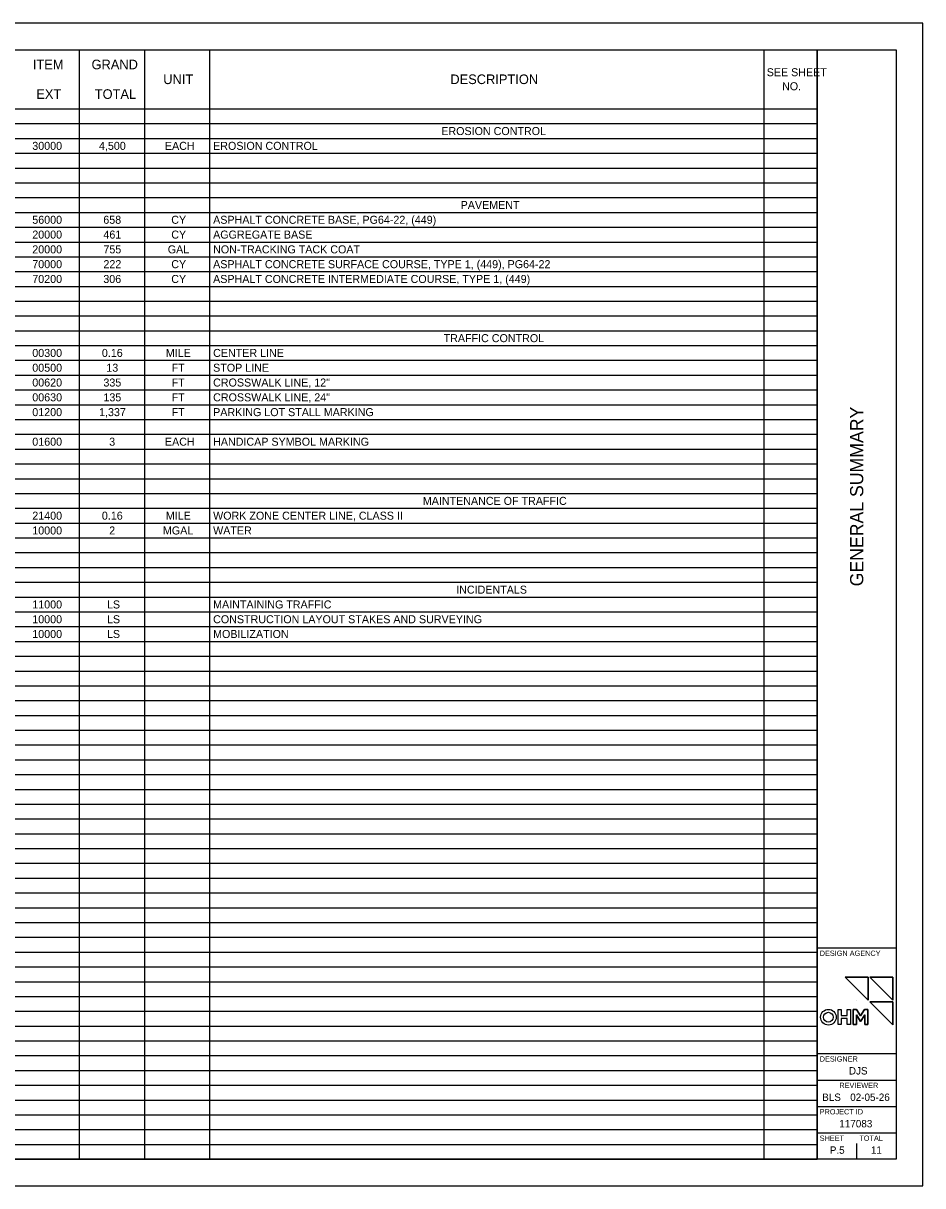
# Model space of a CAD drawing. Extents: x 0 to 34, y 0 to 22.
# Drawn here: x 16.98 to 34, y 0 to 22 of the extents above; entities that cross this region are included whole.
import ezdxf

# ---------------------------------------------------------------- set-up
doc = ezdxf.new("R2010")
doc.units = 0
for name, color, linetype in [('Default', 7, 'Continuous'), ('SH_Border', 7, 'Continuous'), ('SH_Cut_Line', 7, 'Continuous'), ('SH_Data', 7, 'Continuous'), ('TX_P_Misc', 7, 'Continuous')]:
    doc.layers.add(name, color=color, linetype=linetype)

msp = doc.modelspace()

# ---------------------------------------------------------------- linework, layer by layer
at = {"layer": 'Default'}
for p, q in [((1.5, 21.5), (32, 21.5)), ((18.035, 21.5), (18.035, 0.502)), ((19.27, 21.5), (19.27, 0.502)), ((20.505, 21.5), (20.505, 0.502)), ((30.995, 21.5), (30.995, 0.502)), ((32, 21.5), (32, 0.502)), ((1.5, 20.38), (32, 20.38)), ((1.5, 20.1), (32, 20.1)), ((1.5, 19.82), (32, 19.82)), ((1.5, 19.54), (32, 19.54)), ((1.5, 19.26), (32, 19.26)), ((1.5, 18.98), (32, 18.98)), ((1.5, 18.7), (32, 18.7)), ((1.5, 18.42), (32, 18.42)), ((1.5, 18.14), (32, 18.14)), ((1.5, 17.86), (32, 17.86)), ((1.5, 17.58), (32, 17.58)), ((1.5, 17.3), (32, 17.3)), ((1.5, 17.021), (32, 17.021)), ((1.5, 16.741), (32, 16.741)), ((1.5, 16.461), (32, 16.461)), ((1.5, 16.181), (32, 16.181)), ((1.5, 15.901), (32, 15.901)), ((1.5, 15.621), (32, 15.621)), ((1.5, 15.341), (32, 15.341)), ((1.5, 15.061), (32, 15.061)), ((1.5, 14.781), (32, 14.781)), ((1.5, 14.501), (32, 14.501)), ((1.5, 14.221), (32, 14.221)), ((1.5, 13.941), (32, 13.941)), ((1.5, 13.661), (32, 13.661)), ((1.5, 13.381), (32, 13.381)), ((1.5, 13.101), (32, 13.101)), ((1.5, 12.821), (32, 12.821)), ((1.5, 12.541), (32, 12.541)), ((1.5, 12.261), (32, 12.261)), ((1.5, 11.981), (32, 11.981)), ((1.5, 11.701), (32, 11.701)), ((1.5, 11.421), (32, 11.421)), ((1.5, 11.141), (32, 11.141)), ((1.5, 10.861), (32, 10.861)), ((1.5, 10.581), (32, 10.581)), ((1.5, 10.301), (32, 10.301)), ((1.5, 10.021), (32, 10.021)), ((1.5, 9.741), (32, 9.741)), ((1.5, 9.461), (32, 9.461)), ((1.5, 9.181), (32, 9.181)), ((1.5, 8.901), (32, 8.901)), ((1.5, 8.621), (32, 8.621)), ((1.5, 8.342), (32, 8.342)), ((1.5, 8.062), (32, 8.062)), ((1.5, 7.782), (32, 7.782)), ((1.5, 7.502), (32, 7.502)), ((1.5, 7.222), (32, 7.222)), ((1.5, 6.942), (32, 6.942)), ((1.5, 6.662), (32, 6.662)), ((1.5, 6.382), (32, 6.382)), ((1.5, 6.102), (32, 6.102)), ((1.5, 5.822), (32, 5.822)), ((1.5, 5.542), (32, 5.542)), ((1.5, 5.262), (32, 5.262)), ((1.5, 4.982), (32, 4.982)), ((1.5, 4.702), (32, 4.702)), ((1.5, 4.422), (32, 4.422)), ((1.5, 4.142), (32, 4.142)), ((1.5, 3.862), (32, 3.862)), ((1.5, 3.582), (32, 3.582)), ((1.5, 3.302), (32, 3.302)), ((1.5, 3.022), (32, 3.022)), ((1.5, 2.742), (32, 2.742)), ((1.5, 2.462), (32, 2.462)), ((1.5, 2.182), (32, 2.182)), ((1.5, 1.902), (32, 1.902)), ((1.5, 1.622), (32, 1.622)), ((1.5, 1.342), (32, 1.342)), ((1.5, 1.062), (32, 1.062)), ((1.5, 0.782), (32, 0.782)), ((1.5, 0.502), (32, 0.502))]:
    msp.add_line(p, q, dxfattribs=at)
for points in [[(32.966, 3.948), (32.966, 3.51), (32.53, 3.948)], [(33.433, 3.948), (33.433, 3.51), (32.997, 3.948)], [(32.397, 3.333), (32.457, 3.333), (32.457, 3.22), (32.571, 3.22), (32.571, 3.333), (32.631, 3.333), (32.631, 3.052), (32.571, 3.052), (32.571, 3.166), (32.457, 3.166), (32.457, 3.052), (32.397, 3.052)], [(32.9, 3.335), (32.963, 3.335), (32.963, 3.052), (32.903, 3.052), (32.903, 3.233), (32.824, 3.108), (32.745, 3.233), (32.745, 3.052), (32.685, 3.052), (32.685, 3.335), (32.748, 3.335), (32.824, 3.216)], [(33.433, 3.483), (33.433, 3.045), (32.997, 3.483)]]:
    msp.add_lwpolyline(points, close=True, dxfattribs=at)
at = {"layer": 'SH_Border'}
for p, q in [((32, 0.5), (32, 21.5)), ((32, 4.5), (33.5, 4.5)), ((32, 2.5), (33.5, 2.5)), ((32, 2), (33.5, 2)), ((32, 1.5), (33.5, 1.5)), ((32, 1), (33.5, 1))]:
    msp.add_line(p, q, dxfattribs=at)
msp.add_lwpolyline([(1.5, 21.5), (33.5, 21.5), (33.5, 0.5), (1.5, 0.5)], close=True, dxfattribs=at)
at = {"layer": 'SH_Cut_Line'}
msp.add_lwpolyline([(0, 0), (34, 0), (34, 22), (0, 22)], close=True, dxfattribs=at)
at = {"layer": 'SH_Data'}
for p, q in [((32.75, 3.5), (32.75, 3.5)), ((32.375, 0.675), (32.375, 0.675)), ((32.75, 0.5), (32.75, 0.8))]:
    msp.add_line(p, q, dxfattribs=at)
at = {"layer": 'TX_P_Misc'}
for p, q in [((32.745, 3.052), (32.745, 3.233)), ((32.745, 3.233), (32.824, 3.108)), ((32.824, 3.108), (32.903, 3.233)), ((32.903, 3.233), (32.903, 3.052))]:
    msp.add_line(p, q, dxfattribs=at)
for points in [[(32.53, 3.948), (32.966, 3.51), (32.966, 3.948), (32.53, 3.948)], [(32.997, 3.948), (33.433, 3.51), (33.433, 3.948), (32.997, 3.948)], [(32.824, 3.216), (32.748, 3.335), (32.685, 3.335), (32.685, 3.052), (32.745, 3.052)], [(32.903, 3.052), (32.963, 3.052), (32.963, 3.335), (32.9, 3.335), (32.824, 3.216)], [(32.997, 3.483), (33.433, 3.045), (33.433, 3.483), (32.997, 3.483)]]:
    msp.add_lwpolyline(points, dxfattribs=at)
msp.add_lwpolyline([(32.397, 3.333), (32.457, 3.333), (32.457, 3.22), (32.571, 3.22), (32.571, 3.333), (32.631, 3.333), (32.631, 3.052), (32.571, 3.052), (32.571, 3.166), (32.457, 3.166), (32.457, 3.052), (32.397, 3.052)], close=True, dxfattribs=at)
for radius in [0.148, 0.148, 0.0927, 0.0927]:
    msp.add_circle((32.215, 3.19), radius, dxfattribs=at)

# ---------------------------------------------------------------- texts
at = {"layer": 'Default'}
for s, height, p in [('ITEM', 0.1818, (17.159, 21.129)), ('GRAND', 0.1818, (18.27, 21.129)), ('SEE SHEET ', 0.1515, (31.047, 20.997)), ('UNIT', 0.1818, (19.627, 20.849)), ('DESCRIPTION', 0.18181, (25.06, 20.849)), ('EXT', 0.1818, (17.225, 20.569)), ('TOTAL', 0.1818, (18.331, 20.569)), ('NO.', 0.1515, (31.338, 20.732)), ('EROSION CONTROL', 0.15151, (24.889, 19.884)), ('30000', 0.1515, (17.149, 19.604)), ('4,500', 0.1515, (18.411, 19.604)), ('EACH', 0.1515, (19.659, 19.604)), ('EROSION CONTROL', 0.15151, (20.571, 19.604)), ('PAVEMENT', 0.1515, (25.255, 18.485)), ('56000', 0.1515, (17.149, 18.205)), ('658', 0.1515, (18.493, 18.205)), ('CY', 0.1515, (19.779, 18.205)), ('ASPHALT CONCRETE BASE, PG64-22, (449)', 0.15151, (20.571, 18.205)), ('20000', 0.1515, (17.149, 17.925)), ('461', 0.1515, (18.495, 17.925)), ('CY', 0.1515, (19.779, 17.925)), ('AGGREGATE BASE', 0.15151, (20.571, 17.925)), ('20000', 0.1515, (17.149, 17.645)), ('755', 0.1515, (18.495, 17.645)), ('GAL', 0.1515, (19.713, 17.645)), ('NON-TRACKING TACK COAT', 0.15151, (20.571, 17.645)), ('70000', 0.1515, (17.149, 17.365)), ('222', 0.1515, (18.495, 17.365)), ('CY', 0.1515, (19.779, 17.365)), ('ASPHALT CONCRETE SURFACE COURSE, TYPE 1, (449), PG64-22', 0.15151, (20.571, 17.365)), ('70200', 0.1515, (17.149, 17.085)), ('306', 0.1515, (18.493, 17.085)), ('CY', 0.1515, (19.779, 17.085)), ('ASPHALT CONCRETE INTERMEDIATE COURSE, TYPE 1, (449)', 0.15151, (20.571, 17.085)), ('TRAFFIC CONTROL', 0.15151, (24.933, 15.965)), ('00300', 0.1515, (17.149, 15.685)), ('0.16', 0.1515, (18.466, 15.685)), ('MILE', 0.1515, (19.676, 15.685)), ('CENTER LINE', 0.15151, (20.571, 15.685)), ('00500', 0.1515, (17.149, 15.405)), ('13', 0.1515, (18.55, 15.405)), ('FT', 0.1515, (19.786, 15.405)), ('STOP LINE', 0.1515, (20.571, 15.405)), ('00620', 0.1515, (17.149, 15.125)), ('335', 0.1515, (18.495, 15.125)), ('FT', 0.1515, (19.786, 15.125)), ('CROSSWALK LINE, 12"', 0.15151, (20.571, 15.125)), ('00630', 0.1515, (17.149, 14.845)), ('135', 0.1515, (18.495, 14.845)), ('FT', 0.1515, (19.786, 14.845)), ('CROSSWALK LINE, 24"', 0.15151, (20.571, 14.845)), ('01200', 0.1515, (17.149, 14.565)), ('1,337', 0.1515, (18.413, 14.565)), ('FT', 0.1515, (19.786, 14.565)), ('PARKING LOT STALL MARKING', 0.15151, (20.571, 14.565)), ('01600', 0.1515, (17.149, 14.005)), ('3', 0.152, (18.604, 14.005)), ('EACH', 0.1515, (19.659, 14.005)), ('HANDICAP SYMBOL MARKING', 0.15151, (20.571, 14.005)), ('MAINTENANCE OF TRAFFIC', 0.15151, (24.539, 12.885)), ('21400', 0.1515, (17.149, 12.605)), ('0.16', 0.1515, (18.466, 12.605)), ('MILE', 0.1515, (19.676, 12.605)), ('WORK ZONE CENTER LINE, CLASS II', 0.15151, (20.571, 12.605)), ('10000', 0.1515, (17.149, 12.325)), ('2', 0.152, (18.604, 12.325)), ('MGAL', 0.1515, (19.621, 12.325)), ('WATER', 0.1515, (20.571, 12.325)), ('INCIDENTALS', 0.15151, (25.171, 11.205)), ('11000', 0.1515, (17.149, 10.925)), ('LS', 0.1515, (18.562, 10.925)), ('MAINTAINING TRAFFIC', 0.15151, (20.571, 10.925)), ('10000', 0.1515, (17.149, 10.645)), ('LS', 0.1515, (18.562, 10.645)), ('CONSTRUCTION LAYOUT STAKES AND SURVEYING', 0.15151, (20.571, 10.645)), ('10000', 0.1515, (17.149, 10.366)), ('LS', 0.1515, (18.562, 10.366)), ('MOBILIZATION', 0.15151, (20.571, 10.366))]:
    msp.add_text(s, height=height, dxfattribs=at).set_placement(p)
at = {"layer": 'SH_Data'}
msp.add_text('GENERAL SUMMARY', height=0.25, rotation=90, dxfattribs=at).set_placement((32.875, 11.344))
for s, height, p in [('DESIGN AGENCY', 0.1, (32.05, 4.35)), ('DESIGNER', 0.1, (32.05, 2.35)), ('DJS', 0.14, (32.602, 2.105)), ('REVIEWER', 0.1, (32.422, 1.85)), ('BLS', 0.14, (32.097, 1.605)), ('02-05-26', 0.14, (32.627, 1.605)), ('PROJECT ID', 0.1, (32.05, 1.35)), ('117083', 0.14, (32.421, 1.105)), ('SHEET', 0.1, (32.05, 0.85)), ('TOTAL', 0.1, (32.8, 0.85)), ('P.5', 0.14, (32.241, 0.605)), ('11', 0.14, (33.019, 0.605))]:
    msp.add_text(s, height=height, dxfattribs=at).set_placement(p)

doc.saveas('drawing.dxf')
